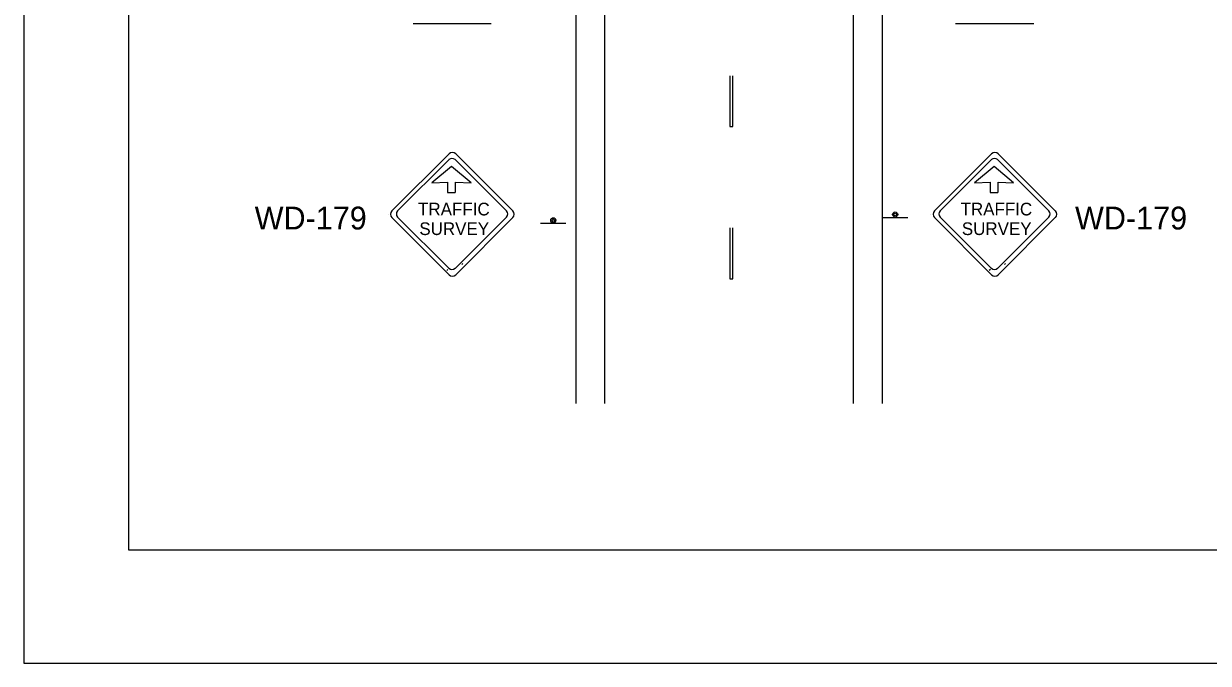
# Model space of a CAD drawing. Extents: x 1314 to 1530, y 165 to 444.
# Drawn here: x 1313.8 to 1426.7, y 164.9 to 225.9 of the extents above; entities that cross this region are included whole.
import ezdxf

# ---------------------------------------------------------------- set-up
doc = ezdxf.new("R2010")
doc.units = 0
for name, color, linetype in [('Level 10', 7, 'Continuous'), ('Level 2', 7, 'Continuous'), ('Level 44', 7, 'Continuous'), ('Level 60', 7, 'Continuous')]:
    doc.layers.add(name, color=color, linetype=linetype)

msp = doc.modelspace()

# ---------------------------------------------------------------- linework, layer by layer
at = {"layer": 'Level 10'}
for p, q in [((1366.45, 414.01), (1366.45, 189.64)), ((1369.18, 414.01), (1369.18, 189.64)), ((1392.88, 414.01), (1392.88, 189.64)), ((1395.63, 414.01), (1395.63, 189.64)), ((1366.45, 205.36), (1366.45, 205.36))]:
    msp.add_line(p, q, dxfattribs=at)
at = {"layer": 'Level 2'}
for p, q in [((1381.11, 220.89), (1381.11, 216.05)), ((1381.4, 216.05), (1381.4, 220.89)), ((1381.11, 216.05), (1381.4, 216.05)), ((1381.11, 206.38), (1381.11, 201.54)), ((1381.4, 201.54), (1381.4, 206.38)), ((1354.23, 202.42), (1354.13, 202.32)), ((1355.68, 202.99), (1355.57, 202.88)), ((1405.94, 202.42), (1405.83, 202.32)), ((1407.38, 202.99), (1407.28, 202.88)), ((1381.11, 201.54), (1381.4, 201.54))]:
    msp.add_line(p, q, dxfattribs=at)
at = {"layer": 'Level 44'}
for p, q in [((1358.37, 225.85), (1350.92, 225.85)), ((1410.08, 225.85), (1402.63, 225.85)), ((1354.35, 213.44), (1348.9, 208)), ((1360.42, 208), (1354.99, 213.44)), ((1406.05, 213.44), (1400.61, 208)), ((1412.13, 208), (1406.69, 213.44)), ((1349.45, 208), (1354.35, 212.89)), ((1354.59, 212.25), (1352.71, 210.67)), ((1356.45, 210.67), (1354.59, 212.25)), ((1354.92, 212.89), (1359.82, 208)), ((1401.15, 208), (1406.05, 212.89)), ((1406.29, 212.25), (1404.42, 210.67)), ((1408.16, 210.67), (1406.29, 212.25)), ((1406.63, 212.89), (1411.52, 208)), ((1352.71, 210.67), (1354.21, 210.75)), ((1354.21, 210.75), (1354.21, 209.76)), ((1354.96, 209.76), (1354.96, 210.75)), ((1354.96, 210.75), (1356.45, 210.67)), ((1404.42, 210.67), (1405.92, 210.75)), ((1405.92, 210.75), (1405.92, 209.76)), ((1406.67, 209.76), (1406.67, 210.75)), ((1406.67, 210.75), (1408.16, 210.67)), ((1354.21, 209.76), (1354.95, 209.76)), ((1405.92, 209.76), (1406.66, 209.76)), ((1348.58, 207.69), (1348.58, 207.69)), ((1348.9, 207.36), (1354.35, 201.92)), ((1348.91, 207.36), (1348.9, 207.36)), ((1354.35, 202.52), (1349.45, 207.42)), ((1359.82, 207.42), (1354.92, 202.52)), ((1354.99, 201.92), (1360.42, 207.36)), ((1363.07, 206.84), (1365.49, 206.84)), ((1395.66, 207.38), (1398.08, 207.38)), ((1400.28, 207.69), (1400.28, 207.69)), ((1400.61, 207.36), (1406.05, 201.92)), ((1400.61, 207.36), (1400.61, 207.36)), ((1406.05, 202.52), (1401.15, 207.42)), ((1411.52, 207.42), (1406.63, 202.52)), ((1406.69, 201.92), (1412.13, 207.36))]:
    msp.add_line(p, q, dxfattribs=at)
for centre, radius in [((1396.87, 207.66), 0.242), ((1396.87, 207.66), 0.121), ((1364.29, 207.11), 0.242), ((1364.29, 207.11), 0.121)]:
    msp.add_circle(centre, radius, dxfattribs=at)
for centre, radius, start, end in [((1354.67, 213.12), 0.455, 45, 135), ((1406.37, 213.12), 0.455, 45, 135), ((1354.63, 212.6), 0.41, 45, 135), ((1406.34, 212.6), 0.41, 45, 135), ((1349.23, 207.68), 0.455, 135, 225), ((1349.74, 207.71), 0.41, 135, 225), ((1359.53, 207.71), 0.41, 315, 45), ((1360.1, 207.68), 0.455, 315, 45), ((1400.93, 207.68), 0.455, 135, 225), ((1401.45, 207.71), 0.41, 135, 225), ((1411.23, 207.71), 0.41, 315, 45), ((1411.81, 207.68), 0.455, 315, 45), ((1354.63, 202.82), 0.41, 225, 315), ((1406.34, 202.82), 0.41, 225, 315), ((1354.67, 202.24), 0.455, 225, 315), ((1406.37, 202.24), 0.455, 225, 315)]:
    msp.add_arc(centre, radius, start, end, dxfattribs=at)
at = {"layer": 'Level 60'}
for p, q in [((1323.82, 175.68), (1323.82, 175.68)), ((1313.82, 164.87), (1313.82, 164.87))]:
    msp.add_line(p, q, dxfattribs=at)
for points in [[(1529.82, 443.87), (1313.82, 443.87), (1313.82, 164.87), (1529.82, 164.87)], [(1510.69, 433.06), (1323.82, 433.06), (1323.82, 175.68), (1510.69, 175.68)]]:
    msp.add_lwpolyline(points, close=True, dxfattribs=at)

# ---------------------------------------------------------------- texts
at = {"layer": 'Level 10'}
for p in [(1335.83, 206.23), (1414.01, 206.23)]:
    msp.add_text('WD-179', height=2.177, rotation=360, dxfattribs=at).set_placement(p)
at = {"layer": 'Level 44'}
for s, p in [('TRAFFIC', (1351.4, 207.57)), ('TRAFFIC', (1403.1, 207.57)), ('SURVEY', (1351.52, 205.7)), ('SURVEY', (1403.22, 205.7))]:
    msp.add_text(s, height=1.209, rotation=360, dxfattribs=at).set_placement(p)

doc.saveas('drawing.dxf')
